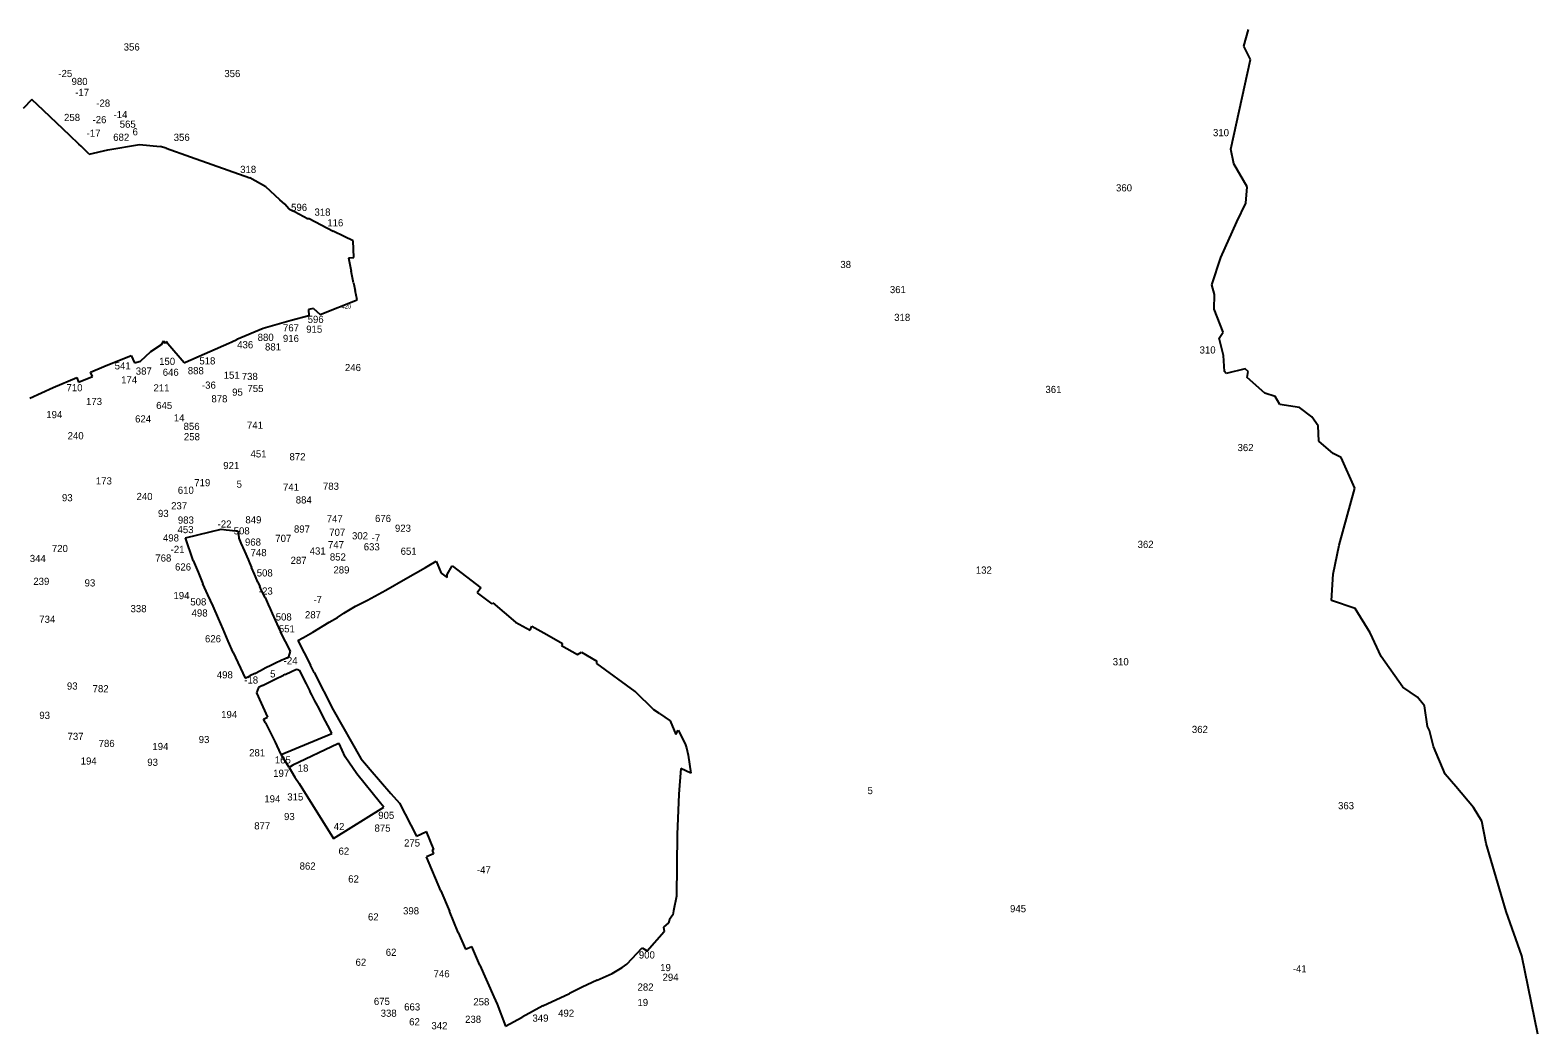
# Model space of a CAD drawing. Extents: x -782977 to -778030, y -975420 to -964838.
# Drawn here: x -780729 to -779276, y -974686 to -973722 of the extents above; entities that cross this region are included whole.
import ezdxf

# ---------------------------------------------------------------- set-up
doc = ezdxf.new("R2010")
doc.units = 0
doc.layers.add('Vrstva 13', color=7, linetype='Continuous')
doc.layers.add('Vrstva 24', color=7, linetype='Continuous')

msp = doc.modelspace()

# ---------------------------------------------------------------- linework, layer by layer
at = {"layer": 'Vrstva 13'}
for p, q in [((-779559.52, -973737.08), (-779555.15, -973721)), ((-779553.01, -973750), (-779559.52, -973737.08)), ((-779572.2, -973836.62), (-779553.01, -973750)), ((-780727.68, -973788.73), (-780736.08, -973797.35)), ((-780716.45, -973799.16), (-780727.68, -973788.73)), ((-780691.03, -973823.29), (-780716.45, -973799.16)), ((-780682.19, -973831.69), (-780691.03, -973823.29)), ((-780680.17, -973833.71), (-780682.19, -973831.69)), ((-780654.34, -973837.21), (-780623.92, -973831.99)), ((-780623.92, -973831.99), (-780603.82, -973833.8)), ((-780672.3, -973841.38), (-780680.17, -973833.71)), ((-780672.3, -973841.38), (-780654.34, -973837.21)), ((-780598.27, -973835.41), (-780603.82, -973833.8)), ((-780598.27, -973835.41), (-780574.7, -973843.76)), ((-780574.7, -973843.76), (-780517.44, -973864.01)), ((-779569.05, -973850.5), (-779572.2, -973836.62)), ((-779556.18, -973872.84), (-779569.05, -973850.5)), ((-780502.05, -973872.87), (-780517.44, -973864.01)), ((-780488.47, -973885.39), (-780502.05, -973872.87)), ((-779557.68, -973888.59), (-779556.18, -973872.84)), ((-780483.71, -973889.66), (-780488.47, -973885.39)), ((-780480.08, -973893.91), (-780483.71, -973889.66)), ((-779566.12, -973906.6), (-779557.68, -973888.59)), ((-780480.08, -973893.91), (-780475.51, -973896.33)), ((-780471.09, -973898.87), (-780475.51, -973896.33)), ((-780464.93, -973902.2), (-780471.09, -973898.87)), ((-780462.61, -973903.42), (-780464.93, -973902.2)), ((-780462.61, -973903.42), (-780460.22, -973903.33)), ((-780460.22, -973903.33), (-780437.16, -973915.57)), ((-780426.66, -973920.79), (-780437.16, -973915.57)), ((-779581.58, -973941.08), (-779566.12, -973906.6)), ((-780417.96, -973925), (-780426.66, -973920.79)), ((-780417.16, -973941.02), (-780417.96, -973925)), ((-780422.45, -973941.39), (-780417.16, -973941.02)), ((-780422.45, -973941.39), (-780419.77, -973954.29)), ((-779590.23, -973967.33), (-779581.58, -973941.08)), ((-780417.74, -973965.32), (-780419.77, -973954.29)), ((-780417.74, -973965.32), (-780416.15, -973972.64)), ((-780414.19, -973981.85), (-780416.15, -973972.64)), ((-779587.78, -973976.59), (-779590.23, -973967.33)), ((-779588.09, -973990.63), (-779587.78, -973976.59)), ((-780459.31, -973990.74), (-780460.94, -973991.21)), ((-780460.94, -973991.21), (-780460.72, -973997.23)), ((-780456.08, -973990.11), (-780459.31, -973990.74)), ((-780456.08, -973990.11), (-780449.63, -973996.06)), ((-780449.63, -973996.06), (-780414.19, -973981.85)), ((-779579.44, -974012.91), (-779588.09, -973990.63)), ((-780477.65, -974001.87), (-780504.71, -974009.53)), ((-780460.72, -973997.23), (-780477.65, -974001.87)), ((-780602.63, -974024.82), (-780600.34, -974021.17)), ((-780599.22, -974023.86), (-780600.34, -974021.17)), ((-780534.82, -974022.22), (-780529.92, -974020.15)), ((-780504.71, -974009.53), (-780529.92, -974020.15)), ((-779583.31, -974018.61), (-779579.44, -974012.91)), ((-779579.04, -974035.4), (-779583.31, -974018.61)), ((-780658.21, -974046.08), (-780631.93, -974035.6)), ((-780631.93, -974035.6), (-780628.79, -974042.54)), ((-780622.84, -974040.9), (-780612.85, -974031.52)), ((-780612.85, -974031.52), (-780602.63, -974024.82)), ((-780597.55, -974022.12), (-780599.22, -974023.86)), ((-780596.66, -974024.1), (-780597.55, -974022.12)), ((-780580.71, -974042.4), (-780596.66, -974024.1)), ((-780579.56, -974041.84), (-780537.9, -974023.5)), ((-780537.9, -974023.5), (-780534.82, -974022.22)), ((-779578.12, -974050.76), (-779579.04, -974035.4)), ((-780671.17, -974051.47), (-780658.21, -974046.08)), ((-780628.79, -974042.54), (-780622.84, -974040.9)), ((-780580.71, -974042.4), (-780579.56, -974041.84)), ((-779558.09, -974048.42), (-779576.5, -974052.69)), ((-779555.44, -974050.96), (-779558.09, -974048.42)), ((-780707.15, -974066.25), (-780684.42, -974056.78)), ((-780684.42, -974056.78), (-780682.6, -974061.23)), ((-780682.6, -974061.23), (-780669.21, -974055.84)), ((-780669.21, -974055.84), (-780671.17, -974051.47)), ((-779576.5, -974052.69), (-779578.12, -974050.76)), ((-779556.16, -974056.66), (-779555.44, -974050.96)), ((-779539.43, -974071.62), (-779556.16, -974056.66)), ((-780729.57, -974076.59), (-780707.15, -974066.25)), ((-779529.31, -974075.08), (-779539.43, -974071.62)), ((-779524.78, -974082.66), (-779529.31, -974075.08)), ((-779505.77, -974085.71), (-779524.78, -974082.66)), ((-779494.07, -974094.46), (-779505.77, -974085.71)), ((-779487.97, -974103.42), (-779494.07, -974094.46)), ((-779487.36, -974118.01), (-779487.97, -974103.42)), ((-779473.43, -974129.86), (-779487.36, -974118.01)), ((-779465.55, -974133.83), (-779473.43, -974129.86)), ((-779452.54, -974163.51), (-779465.55, -974133.83)), ((-779467.52, -974218.47), (-779452.54, -974163.51)), ((-780579.61, -974211.39), (-780555.62, -974205.49)), ((-780555.62, -974205.49), (-780545.13, -974202.89)), ((-780545.13, -974202.89), (-780540.21, -974203.46)), ((-780540.21, -974203.46), (-780530.95, -974204.41)), ((-780530.95, -974204.41), (-780528.7, -974204.77)), ((-780528.7, -974204.77), (-780528.24, -974211.66)), ((-780572.19, -974233.14), (-780579.61, -974211.39)), ((-780528.24, -974211.66), (-780526.1, -974216.42)), ((-780526.1, -974216.42), (-780522.77, -974224.24)), ((-780522.77, -974224.24), (-780519.26, -974232.16)), ((-779473.36, -974246.2), (-779467.52, -974218.47)), ((-780572.19, -974233.14), (-780567.39, -974244.3)), ((-780519.26, -974232.16), (-780517.75, -974235.5)), ((-780517.75, -974235.5), (-780515.95, -974239.82)), ((-780348.11, -974239.72), (-780345.07, -974237.98)), ((-780345.07, -974237.98), (-780338.04, -974233.92)), ((-780338.04, -974233.92), (-780333.25, -974245.3)), ((-780327.24, -974246.61), (-780322.67, -974238.41)), ((-780322.67, -974238.41), (-780295.05, -974259.52)), ((-780567.39, -974244.3), (-780562.95, -974255.48)), ((-780512.9, -974246.42), (-780515.95, -974239.82)), ((-780509.68, -974253.9), (-780512.9, -974246.42)), ((-780509.68, -974253.9), (-780507.76, -974258.04)), ((-780386.45, -974261.57), (-780367.46, -974250.92)), ((-780367.46, -974250.92), (-780348.11, -974239.72)), ((-780333.25, -974245.3), (-780327.38, -974249.36)), ((-780327.38, -974249.36), (-780327.24, -974246.61)), ((-779475.06, -974271.58), (-779473.36, -974246.2)), ((-780557.9, -974266.14), (-780562.95, -974255.48)), ((-780552.97, -974277.26), (-780557.9, -974266.14)), ((-780506.18, -974262.02), (-780507.76, -974258.04)), ((-780502.88, -974268.79), (-780506.18, -974262.02)), ((-780404.07, -974271.45), (-780386.45, -974261.57)), ((-780295.05, -974259.52), (-780298.53, -974264.23)), ((-780298.53, -974264.23), (-780284.25, -974275.03)), ((-780547.77, -974289.12), (-780552.97, -974277.26)), ((-780502.88, -974268.79), (-780499.83, -974275.6)), ((-780499.83, -974275.6), (-780498.07, -974279.86)), ((-780498.07, -974279.86), (-780496.02, -974284.29)), ((-780426.79, -974283.85), (-780415.78, -974277.29)), ((-780415.78, -974277.29), (-780404.07, -974271.45)), ((-780284.25, -974275.03), (-780283.45, -974273.95)), ((-780283.45, -974273.95), (-780261.57, -974292.65)), ((-779452.28, -974279.51), (-779475.06, -974271.58)), ((-779437.64, -974303.01), (-779452.28, -974279.51)), ((-780543.24, -974299.42), (-780547.77, -974289.12)), ((-780496.02, -974284.29), (-780493.14, -974290.68)), ((-780493.14, -974290.68), (-780489.84, -974297.66)), ((-780489.84, -974297.66), (-780487.88, -974301.92)), ((-780456.8, -974302.34), (-780441.08, -974292.73)), ((-780441.08, -974292.73), (-780433.2, -974287.98)), ((-780433.2, -974287.98), (-780426.79, -974283.85)), ((-780261.57, -974292.65), (-780247.5, -974300.45)), ((-780247.5, -974300.45), (-780245.76, -974296.32)), ((-780245.76, -974296.32), (-780231.34, -974304.51)), ((-780538.48, -974310.92), (-780543.24, -974299.42)), ((-780533.72, -974321.86), (-780538.48, -974310.92)), ((-780478.39, -974320.62), (-780487.88, -974301.92)), ((-780471.19, -974310.19), (-780465.9, -974307.41)), ((-780471.19, -974310.19), (-780459.16, -974334.12)), ((-780465.9, -974307.41), (-780456.8, -974302.34)), ((-780231.34, -974304.51), (-780216.26, -974313.07)), ((-779427.09, -974325.78), (-779437.64, -974303.01)), ((-780533.72, -974321.86), (-780522.13, -974346.65)), ((-780483.45, -974327.6), (-780480.02, -974326.01)), ((-780480.02, -974326.01), (-780478.39, -974320.62)), ((-780216.26, -974313.07), (-780217.2, -974314.95)), ((-780217.2, -974314.95), (-780201.69, -974323.73)), ((-780201.69, -974323.73), (-780197.78, -974321.56)), ((-780197.78, -974321.56), (-780183.21, -974330.33)), ((-779406.25, -974355.18), (-779427.09, -974325.78)), ((-780512.73, -974341.93), (-780507.14, -974339.04)), ((-780507.14, -974339.04), (-780502, -974336.45)), ((-780502, -974336.45), (-780497.2, -974334.07)), ((-780497.2, -974334.07), (-780492.69, -974331.73)), ((-780492.69, -974331.73), (-780487.34, -974329.31)), ((-780487.34, -974329.31), (-780483.45, -974327.6)), ((-780483.4, -974343), (-780477.3, -974340.07)), ((-780477.3, -974340.07), (-780472.66, -974337.98)), ((-780472.66, -974337.98), (-780471.24, -974338.15)), ((-780471.24, -974338.15), (-780469.9, -974338.86)), ((-780469.9, -974338.86), (-780463.3, -974352.19)), ((-780455.66, -974340.96), (-780459.16, -974334.12)), ((-780455.66, -974340.96), (-780437.17, -974377.06)), ((-780183.12, -974332.51), (-780183.21, -974330.33)), ((-780146.16, -974359.41), (-780183.12, -974332.51)), ((-780522.13, -974346.65), (-780517.47, -974344.28)), ((-780512.73, -974341.93), (-780517.47, -974344.28)), ((-780509.23, -974355.67), (-780511.06, -974360.69)), ((-780505.3, -974353.58), (-780509.23, -974355.67)), ((-780505.3, -974353.58), (-780493.1, -974347.48)), ((-780493.1, -974347.48), (-780485.03, -974343.79)), ((-780483.4, -974343), (-780485.03, -974343.79)), ((-780463.3, -974352.19), (-780459.71, -974359.09)), ((-779392.26, -974364.79), (-779406.25, -974355.18)), ((-780511.06, -974360.69), (-780500.47, -974384.27)), ((-780457.79, -974362.81), (-780459.71, -974359.09)), ((-780454.84, -974368.31), (-780457.79, -974362.81)), ((-780452.39, -974372.91), (-780454.84, -974368.31)), ((-780128.04, -974377.12), (-780146.16, -974359.41)), ((-779385.45, -974373.39), (-779392.26, -974364.79)), ((-780504.29, -974386.08), (-780500.47, -974384.27)), ((-780452, -974373.64), (-780452.39, -974372.91)), ((-780450.47, -974376.44), (-780452, -974373.64)), ((-780446.14, -974385.08), (-780450.47, -974376.44)), ((-780437.17, -974377.06), (-780410.56, -974423.95)), ((-780122.8, -974380.62), (-780128.04, -974377.12)), ((-780122.8, -974380.62), (-780112.32, -974387.68)), ((-779382.57, -974393.31), (-779385.45, -974373.39)), ((-780502.42, -974389.72), (-780504.29, -974386.08)), ((-780502.42, -974389.72), (-780493.19, -974408.14)), ((-780444.76, -974387.93), (-780446.14, -974385.08)), ((-780440.21, -974396.52), (-780444.76, -974387.93)), ((-780438.6, -974400.09), (-780440.21, -974396.52)), ((-780112.32, -974387.68), (-780107.04, -974400.75)), ((-780107.04, -974400.75), (-780104.74, -974396.62)), ((-780104.74, -974396.62), (-780097.82, -974410.05)), ((-779380.54, -974396.97), (-779382.57, -974393.31)), ((-779376.57, -974412.54), (-779380.54, -974396.97)), ((-780493.19, -974408.14), (-780488.01, -974419.59)), ((-780487.42, -974420.32), (-780438.6, -974400.09)), ((-780432.7, -974409.89), (-780476.2, -974430.6)), ((-780431.58, -974409.57), (-780432.7, -974409.89)), ((-780425.8, -974422.57), (-780431.58, -974409.57)), ((-780097.82, -974410.05), (-780096.7, -974413.89)), ((-780096.7, -974413.89), (-780095.06, -974420.67)), ((-779365.49, -974439.19), (-779376.57, -974412.54)), ((-780488.01, -974419.59), (-780487.42, -974420.32)), ((-780479.77, -974432.81), (-780487.42, -974420.32)), ((-780414.25, -974438.95), (-780425.8, -974422.57)), ((-780410.56, -974423.95), (-780401.59, -974434.65)), ((-780095.06, -974420.67), (-780092.39, -974438.2)), ((-780476.2, -974430.6), (-780479.77, -974432.81)), ((-780479.77, -974432.81), (-780474.07, -974442.04)), ((-780474.07, -974442.04), (-780469.94, -974448.26)), ((-780391.62, -974467.21), (-780414.25, -974438.95)), ((-780401.59, -974434.65), (-780381.62, -974457.81)), ((-780101.98, -974433.81), (-780103.92, -974458.31)), ((-780092.39, -974438.2), (-780101.98, -974433.81)), ((-779355.29, -974451.07), (-779365.49, -974439.19)), ((-780469.94, -974448.26), (-780436.88, -974501.08)), ((-779338.05, -974471.22), (-779355.29, -974451.07)), ((-780436.88, -974501.08), (-780388.25, -974470.9)), ((-780388.25, -974470.9), (-780391.62, -974467.21)), ((-780381.62, -974457.81), (-780373.19, -974467)), ((-780373.19, -974467), (-780367.75, -974477.6)), ((-780103.92, -974458.31), (-780105.56, -974497.41)), ((-779330.07, -974484.44), (-779338.05, -974471.22)), ((-780367.75, -974477.6), (-780356.8, -974498.99)), ((-779325.9, -974506.16), (-779330.07, -974484.44)), ((-780356.8, -974498.99), (-780347.42, -974494.45)), ((-780340.13, -974511.68), (-780347.42, -974494.45)), ((-780105.56, -974497.41), (-780106.38, -974556.71)), ((-780340.13, -974511.68), (-780341.8, -974512.41)), ((-780341.8, -974512.41), (-780340.42, -974516.03)), ((-779306.81, -974571.56), (-779325.9, -974506.16)), ((-780340.42, -974516.03), (-780347.23, -974518.93)), ((-780333.46, -974551.49), (-780347.23, -974518.93)), ((-780333.46, -974551.49), (-780325.05, -974571.14)), ((-780106.38, -974556.71), (-780109.13, -974570.9)), ((-780316.64, -974591.85), (-780325.05, -974571.14)), ((-780109.13, -974570.9), (-780109.74, -974574.68)), ((-779291.56, -974614.39), (-779306.81, -974571.56)), ((-780114.03, -974582.43), (-780118.92, -974586.82)), ((-780118.92, -974586.82), (-780118.21, -974591.01)), ((-780113.11, -974579.17), (-780114.03, -974582.43)), ((-780109.74, -974574.68), (-780113.11, -974579.17)), ((-780316.64, -974591.85), (-780309.68, -974607.9)), ((-780134.57, -974609.61), (-780118.21, -974591.01)), ((-780309.68, -974607.9), (-780303.7, -974605.26)), ((-780295.83, -974623.19), (-780303.7, -974605.26)), ((-780154.25, -974622.24), (-780139.47, -974606.64)), ((-780139.47, -974606.64), (-780134.57, -974609.61)), ((-779276.15, -974689.93), (-779291.56, -974614.39)), ((-780295.83, -974623.19), (-780282.42, -974653.72)), ((-780182.69, -974637.92), (-780168.29, -974631.5)), ((-780168.29, -974631.5), (-780158.74, -974625.71)), ((-780158.74, -974625.71), (-780154.25, -974622.24)), ((-780197.16, -974644.58), (-780209.6, -974650.52)), ((-780182.69, -974637.92), (-780197.16, -974644.58)), ((-780282.42, -974653.72), (-780279.16, -974660.9)), ((-780279.16, -974660.9), (-780270.97, -974682.08)), ((-780234.99, -974662.67), (-780209.6, -974650.52)), ((-780270.97, -974682.08), (-780254.95, -974673.37)), ((-780234.99, -974662.67), (-780254.95, -974673.37))]:
    msp.add_line(p, q, dxfattribs=at)

# ---------------------------------------------------------------- texts
at = {"layer": 'Vrstva 24'}
for s, height, p in [('356', 6.912, (-780639.119, -973741.402)), ('-25', 6.912, (-780702.076, -973766.995)), ('356', 6.912, (-780542.119, -973767.042)), ('980', 6.912, (-780689.351, -973774.672)), ('-17', 6.912, (-780685.837, -973785.235)), ('-28', 6.912, (-780665.526, -973795.575)), ('258', 6.912, (-780696.582, -973809.372)), ('-14', 6.912, (-780648.903, -973806.595)), ('-17', 6.912, (-780674.787, -973824.495)), ('-26', 6.912, (-780669.144, -973811.465)), ('565', 6.912, (-780642.929, -973815.852)), ('6', 6.912, (-780630.567, -973823.142)), ('310', 6.912, (-779589.248, -973824.002)), ('682', 6.912, (-780649.199, -973828.462)), ('356', 6.912, (-780590.919, -973828.542)), ('318', 6.912, (-780526.845, -973859.452)), ('360', 6.912, (-779682.711, -973877.252)), ('596', 6.912, (-780477.765, -973896.062)), ('318', 6.912, (-780455.235, -973900.632)), ('116', 6.912, (-780442.865, -973910.922)), ('38', 6.912, (-779948.396, -973951.162)), ('361', 6.912, (-779900.651, -973975.332)), ('420', 4, (-780429.117, -973990.15)), ('767', 6.912, (-780485.592, -974012.222)), ('915', 6.912, (-780463.171, -974013.512)), ('596', 6.912, (-780461.805, -974004.062)), ('318', 6.912, (-779896.475, -974002.142)), ('436', 6.912, (-780529.701, -974028.492)), ('880', 6.912, (-780509.985, -974021.372)), ('916', 6.912, (-780485.649, -974022.472)), ('881', 6.912, (-780502.895, -974030.622)), ('310', 6.912, (-779602.148, -974033.552)), ('541', 6.912, (-780647.838, -974048.892)), ('387', 6.912, (-780627.439, -974053.902)), ('150', 6.912, (-780604.958, -974044.542)), ('646', 6.912, (-780601.498, -974055.082)), ('888', 6.912, (-780577.322, -974053.532)), ('518', 6.912, (-780566.175, -974044.092)), ('246', 6.912, (-780425.871, -974050.512)), ('710', 6.912, (-780694.245, -974069.952)), ('174', 6.912, (-780641.575, -974062.402)), ('211', 6.912, (-780610.409, -974070.122)), ('-36', 6.912, (-780563.684, -974067.475)), ('151', 6.912, (-780542.739, -974057.902)), ('738', 6.912, (-780525.299, -974059.112)), ('755', 6.912, (-780519.829, -974070.712)), ('361', 6.912, (-779750.721, -974071.632)), ('173', 6.912, (-780675.402, -974083.242)), ('878', 6.912, (-780554.559, -974080.632)), ('95', 6.912, (-780534.583, -974074.242)), ('194', 6.912, (-780713.715, -974095.882)), ('624', 6.912, (-780628.121, -974100.032)), ('645', 6.912, (-780607.801, -974087.082)), ('14', 6.912, (-780590.823, -974098.972)), ('856', 6.912, (-780581.359, -974107.262)), ('741', 6.912, (-780520.295, -974106.142)), ('240', 6.912, (-780693.137, -974116.262)), ('258', 6.912, (-780581.062, -974117.212)), ('362', 6.912, (-779565.579, -974127.652)), ('451', 6.912, (-780516.848, -974133.762)), ('872', 6.912, (-780479.299, -974136.502)), ('921', 6.912, (-780543.151, -974145.022)), ('173', 6.912, (-780665.902, -974159.812)), ('610', 6.912, (-780586.964, -974168.822)), ('719', 6.912, (-780571.079, -974161.542)), ('5', 6.912, (-780530.28, -974162.962)), ('741', 6.912, (-780485.585, -974165.822)), ('783', 6.912, (-780447.079, -974164.952)), ('93', 6.912, (-780698.603, -974176.012)), ('240', 6.912, (-780626.727, -974174.852)), ('237', 6.912, (-780593.379, -974183.822)), ('884', 6.912, (-780473.265, -974178.132)), ('93', 6.912, (-780606.083, -974191.202)), ('983', 6.912, (-780586.899, -974197.572)), ('-22', 6.912, (-780548.586, -974201.395)), ('849', 6.912, (-780521.821, -974197.292)), ('747', 6.912, (-780443.449, -974196.352)), ('676', 6.912, (-780396.871, -974196.022)), ('498', 6.912, (-780601.271, -974214.772)), ('453', 6.912, (-780587.225, -974206.752)), ('508', 6.912, (-780533.104, -974207.992)), ('707', 6.912, (-780492.988, -974215.212)), ('897', 6.912, (-780474.995, -974206.222)), ('707', 6.912, (-780441.008, -974209.392)), ('302', 6.912, (-780419.064, -974212.772)), ('-7', 6.912, (-780400.108, -974214.705)), ('923', 6.912, (-780377.679, -974205.432)), ('720', 6.912, (-780708.311, -974225.002)), ('-21', 6.912, (-780593.85, -974225.865)), ('968', 6.912, (-780522.225, -974218.772)), ('748', 6.912, (-780516.801, -974228.952)), ('431', 6.912, (-780459.848, -974227.442)), ('747', 6.912, (-780442.199, -974221.352)), ('633', 6.912, (-780407.739, -974223.372)), ('651', 6.912, (-780372.201, -974227.622)), ('362', 6.912, (-779661.889, -974221.022)), ('344', 6.912, (-780729.598, -974234.612)), ('768', 6.912, (-780608.625, -974234.182)), ('626', 6.912, (-780589.615, -974242.792)), ('287', 6.912, (-780478.209, -974236.422)), ('852', 6.912, (-780440.402, -974233.152)), ('289', 6.912, (-780436.969, -974245.622)), ('132', 6.912, (-779817.825, -974245.802)), ('239', 6.912, (-780726.209, -974256.692)), ('93', 6.912, (-780676.793, -974258.162)), ('508', 6.912, (-780510.884, -974248.542)), ('194', 6.912, (-780591.135, -974270.372)), ('-23', 6.912, (-780508.786, -974265.985)), ('-7', 6.912, (-780456.218, -974274.115)), ('338', 6.912, (-780632.502, -974282.982)), ('508', 6.912, (-780574.884, -974276.462)), ('498', 6.912, (-780573.651, -974287.182)), ('287', 6.912, (-780464.389, -974288.892)), ('734', 6.912, (-780720.462, -974293.202)), ('508', 6.912, (-780492.574, -974290.992)), ('551', 6.912, (-780489.575, -974302.442)), ('626', 6.912, (-780560.755, -974312.042)), ('-24', 6.912, (-780484.9, -974333.205)), ('498', 6.912, (-780549.351, -974346.802)), ('5', 6.912, (-780497.96, -974345.892)), ('310', 6.912, (-779685.878, -974334.172)), ('93', 6.912, (-780693.823, -974357.622)), ('782', 6.912, (-780669.039, -974360.222)), ('-18', 6.912, (-780522.92, -974351.805)), ('93', 6.912, (-780720.413, -974385.892)), ('194', 6.912, (-780545.135, -974385.082)), ('737', 6.912, (-780693.215, -974406.142)), ('362', 6.912, (-779609.579, -974399.442)), ('786', 6.912, (-780663.245, -974412.962)), ('194', 6.912, (-780611.445, -974415.912)), ('93', 6.912, (-780566.823, -974409.182)), ('194', 6.912, (-780680.555, -974429.932)), ('93', 6.912, (-780616.353, -974431.132)), ('281', 6.912, (-780518.205, -974421.982)), ('165', 6.912, (-780493.431, -974428.852)), ('197', 6.912, (-780495.019, -974441.742)), ('18', 6.912, (-780471.349, -974436.762)), ('315', 6.912, (-780481.455, -974464.532)), ('5', 6.912, (-779922.18, -974458.402)), ('194', 6.912, (-780503.575, -974466.372)), ('363', 6.912, (-779468.719, -974472.952)), ('877', 6.912, (-780513.305, -974492.412)), ('93', 6.912, (-780484.573, -974483.442)), ('42', 6.912, (-780436.669, -974493.082)), ('905', 6.912, (-780393.771, -974482.282)), ('875', 6.912, (-780397.359, -974494.602)), ('62', 6.912, (-780432.073, -974516.792)), ('275', 6.912, (-780368.919, -974508.912)), ('862', 6.912, (-780469.529, -974531.192)), ('-47', 6.912, (-780298.696, -974534.915)), ('62', 6.912, (-780422.723, -974543.622)), ('62', 6.912, (-780403.693, -974580.232)), ('398', 6.912, (-780369.869, -974574.362)), ('945', 6.912, (-779784.841, -974572.262)), ('62', 6.912, (-780415.653, -974623.912)), ('62', 6.912, (-780386.543, -974614.342)), ('900', 6.912, (-780142.573, -974616.902)), ('746', 6.912, (-780340.398, -974635.052)), ('19', 6.912, (-780122.026, -974629.082)), ('294', 6.912, (-780119.741, -974638.392)), ('-41', 6.912, (-779512.352, -974630.245)), ('282', 6.912, (-780143.852, -974647.872)), ('675', 6.912, (-780397.995, -974661.692)), ('663', 6.912, (-780368.775, -974666.992)), ('258', 6.912, (-780302.132, -974662.092)), ('19', 6.912, (-780143.946, -974662.742)), ('338', 6.912, (-780391.452, -974673.072)), ('62', 6.912, (-780363.983, -974681.372)), ('238', 6.912, (-780310.072, -974678.942)), ('349', 6.912, (-780245.131, -974677.812)), ('492', 6.912, (-780220.401, -974673.032)), ('342', 6.912, (-780342.495, -974685.142))]:
    msp.add_text(s, height=height, dxfattribs=at).set_placement(p)

doc.saveas('drawing.dxf')
